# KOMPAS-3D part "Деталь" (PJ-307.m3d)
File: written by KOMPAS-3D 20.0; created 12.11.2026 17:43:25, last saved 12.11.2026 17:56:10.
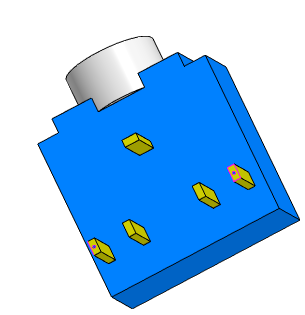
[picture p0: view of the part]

Document properties: Полное имя файла: D:\myProjects\Progect_esp32\box_compas\разъемы\PJ-307.m3d

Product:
- Part/product: Деталь
    Масса: 0.00588277
  - Body: Тело 1
      Масса: 0.00518496

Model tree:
1. Эскиз:1
2. Элемент выдавливания:1
     Расстояние 1 = 5
3. Эскиз:2  (with: Элемент выдавливания:1)
4. Элемент выдавливания:2
     Расстояние 1 = 3.3
5. Эскиз:3  (with: Элемент выдавливания:2)
6. Элемент выдавливания:3
     Расстояние 2 = 4
7. Фаска:1  (with: Элемент выдавливания:3)
     Угол = 45; Длина 1 = 0.5; Длина 2 = 0.5
8. Эскиз:4  (with: Элемент выдавливания:1)
9. Элемент выдавливания:4
     Расстояние 1 = 1
10. Эскиз:5  (with: Элемент выдавливания:1, Элемент выдавливания:2)
11. Элемент выдавливания:5
     Расстояние 1 = 3.5
12. Эскиз:6  (with: Элемент выдавливания:5)
13. Элемент выдавливания:6
     Расстояние 2 = 2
